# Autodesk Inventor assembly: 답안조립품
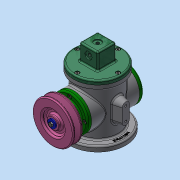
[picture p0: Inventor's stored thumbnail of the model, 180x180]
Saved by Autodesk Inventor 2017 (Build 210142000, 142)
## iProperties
Part Number: 답안조립품
Material: 일반
Document SubType Name: Assembly
Designer: MRC
Author: MRC
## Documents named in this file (18)
- C:\Users\MRC\Desktop\730206V1002\답안조립품.iam
- C:\Users\MRC\Desktop\730206V1002\본체.ipt
- C:\Users\MRC\Desktop\730206V1002\덮개.ipt
- C:\Users\MRC\Desktop\730206V1002\앞커버.ipt
- C:\Users\MRC\Desktop\730206V1002\뒤커버.ipt
- C:\Users\MRC\Desktop\730206V1002\편심축.ipt
- C:\Users\MRC\Desktop\730206V1002\베어링 17 x 40 x 12.ipt
- C:\Users\MRC\Desktop\730206V1002\링크.ipt
- C:\Users\MRC\Desktop\730206V1002\슬라이더.ipt
- C:\Users\MRC\Desktop\730206V1002\클레비스 핀 6 x 22.ipt
- 클레비스 핀 6 x 22.ipt
- C:\Users\MRC\Desktop\730206V1002\E-링.ipt
- C:\Users\MRC\Desktop\730206V1002\오일 실 17 30 8.ipt
- C:\Users\MRC\Desktop\730206V1002\키 4 x 4 x 12.ipt
- C:\Users\MRC\Desktop\730206V1002\V-벨트풀리.ipt
- C:\Users\MRC\Desktop\730206V1002\와셔 4x16.ipt
- C:\Users\MRC\Desktop\730206V1002\볼트 M4 x 10.ipt
- C:\Users\MRC\Desktop\730206V1002\볼트 M4 x 8.ipt
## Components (2 placed, 2 different names)
1. E-링:1
2. V-벨트풀리:1
